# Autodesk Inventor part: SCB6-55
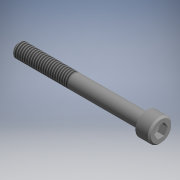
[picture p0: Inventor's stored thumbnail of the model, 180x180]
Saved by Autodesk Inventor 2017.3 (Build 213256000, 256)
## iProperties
Part Number: SCB6-55
Material: Generic
Catalog Web Link: www.cadenas.de
Description: SCB-Hexagon Socket Head Cap Screws - Stainless Steel
Vendor: MISUMI
Document SubType Name: Modeling
Designer: partserver
Manufacturer: MISUMI
Mass: 1.94701 g
Surface Area: 14.1484 cm^2
Volume: 1.94701 cm^3
Density: 1 g/cm^3
Appearance: PSOLRGB-175-175-175
Category: PARTsolutions
Company: MISUMI
Title: SCB6-55
Author: Cadenas PARTsolutions
Comments: Hexagon Socket Head Cap Screws - Stainless Steel
PSOL_IDENT_0: {$CADENAS_DATA\23d-libs\misumi\metric\27_screws_nuts\scb_fa.prj},154 {VTYP=3D},{NB=SCB6-55},{LINA=SC
PSOL_IDENT_1: B6-55},{NN=SCB},{DATE=03.06.2021 03:35:43},{GEOMDATE=23.02.2012 00:00:00},{VERSION=},{LINEID=120},{W
PSOL_IDENT_2: BVAR=L},{WBNUMERIC=L}  {NB=SCB6-55},{LINA=SCB6-55},{KT=DUMMY},{PN=SCB6-55},{MAT=SUSXM7(30430 Stainle
PSOL_IDENT_3: ss Steel)},{SC=A2-70},{M=6},{L=55},{LL=24},{L1=24},{TYPE=SCB},{M1=6.0},{L0=8,10,12,14,15,16,18,20,22
PSOL_IDENT_4: ,25,30,35,40,45,50,55,60,65,70},{MP=6x1},{P=1},{A=10.0},{E=6.0},{B=5.0},{V=0.60}
NB: SCB6-55
NN: SCB
NT: Hexagon Socket Head Cap Screws - Stainless Steel
NBSYN: $PN.
LINA: SCB6-55
CATALOG: Misumi
PN: SCB6-55
MAT: 302HQ Stainless Steel
SC: A2-70
M: 6
L: 55
LL: 24
MP: 6x1
A: 10
E: 6
B: 5
SUPPLIER: MISUMI
ARTICLENO: SCB6-55
BOMINFO: SCB6-55
CREATOR: CADENAS GmbH
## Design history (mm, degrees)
sketch "Sketch_2"
  geometry: L1 (55, 0)-(-6, 0); L2 (-6, 0)-(-6, 4.333); L3 (-6, 4.333)-(-5.333, 5); L4 (-5.333, 5)-(0, 5); L5 (0, 5)-(0, 3); L6 (0, 3)-(54.386, 3); L7 (54.386, 3)-(55, 2.386); L8 (55, 2.386)-(55, 0); L9 (55, 0)-(-6, 0)
  constraints: 18 end point
revolve "Revolution1" sketch "Sketch_2" stored, may be unused: angle "d0" = 360 deg
thread "Thread1" dims "d1" = 23.3865, "d2" = 0
sketch "Sketch2"
  geometry: 1 further point
hole "Hole1" sketch "Sketch2" at (0, 0) diameter "d3" = 5; stored, may be unused: countersink angle "d7" = 90 deg, drill point angle "d9" = 150 deg; dims "d4" = 6, "d5" = 4, "d6" = 2, "d8" = 3
sketch "Sketch_3"
  geometry: L1 (-2.5, -1.443)-(0, -2.887); L2 (0, -2.887)-(2.5, -1.443); L3 (2.5, -1.443)-(2.5, 1.443); L4 (2.5, 1.443)-(0, 2.887); L5 (0, 2.887)-(-2.5, 1.443); L6 (-2.5, 1.443)-(-2.5, -1.443)
  constraints: 12 end point
extrude "Extrusion1" cut sketch "Sketch_3" distance "d10" = 3; taper "d11" = 0 deg
node "bolt_XY"
node "bolt_YZ"
node "bolt_ZX"
node "bolt_X"
node "bolt_Y"
node "bolt_Z"
node "bolt_Center"
node "nut_XY"
node "nut_YZ"
node "nut_ZX"
node "nut_X"
node "nut_Y"
node "nut_Z"
node "nut_Center"
body "Solid1"
other parameters: "d12" = 0, "d13" = 0
